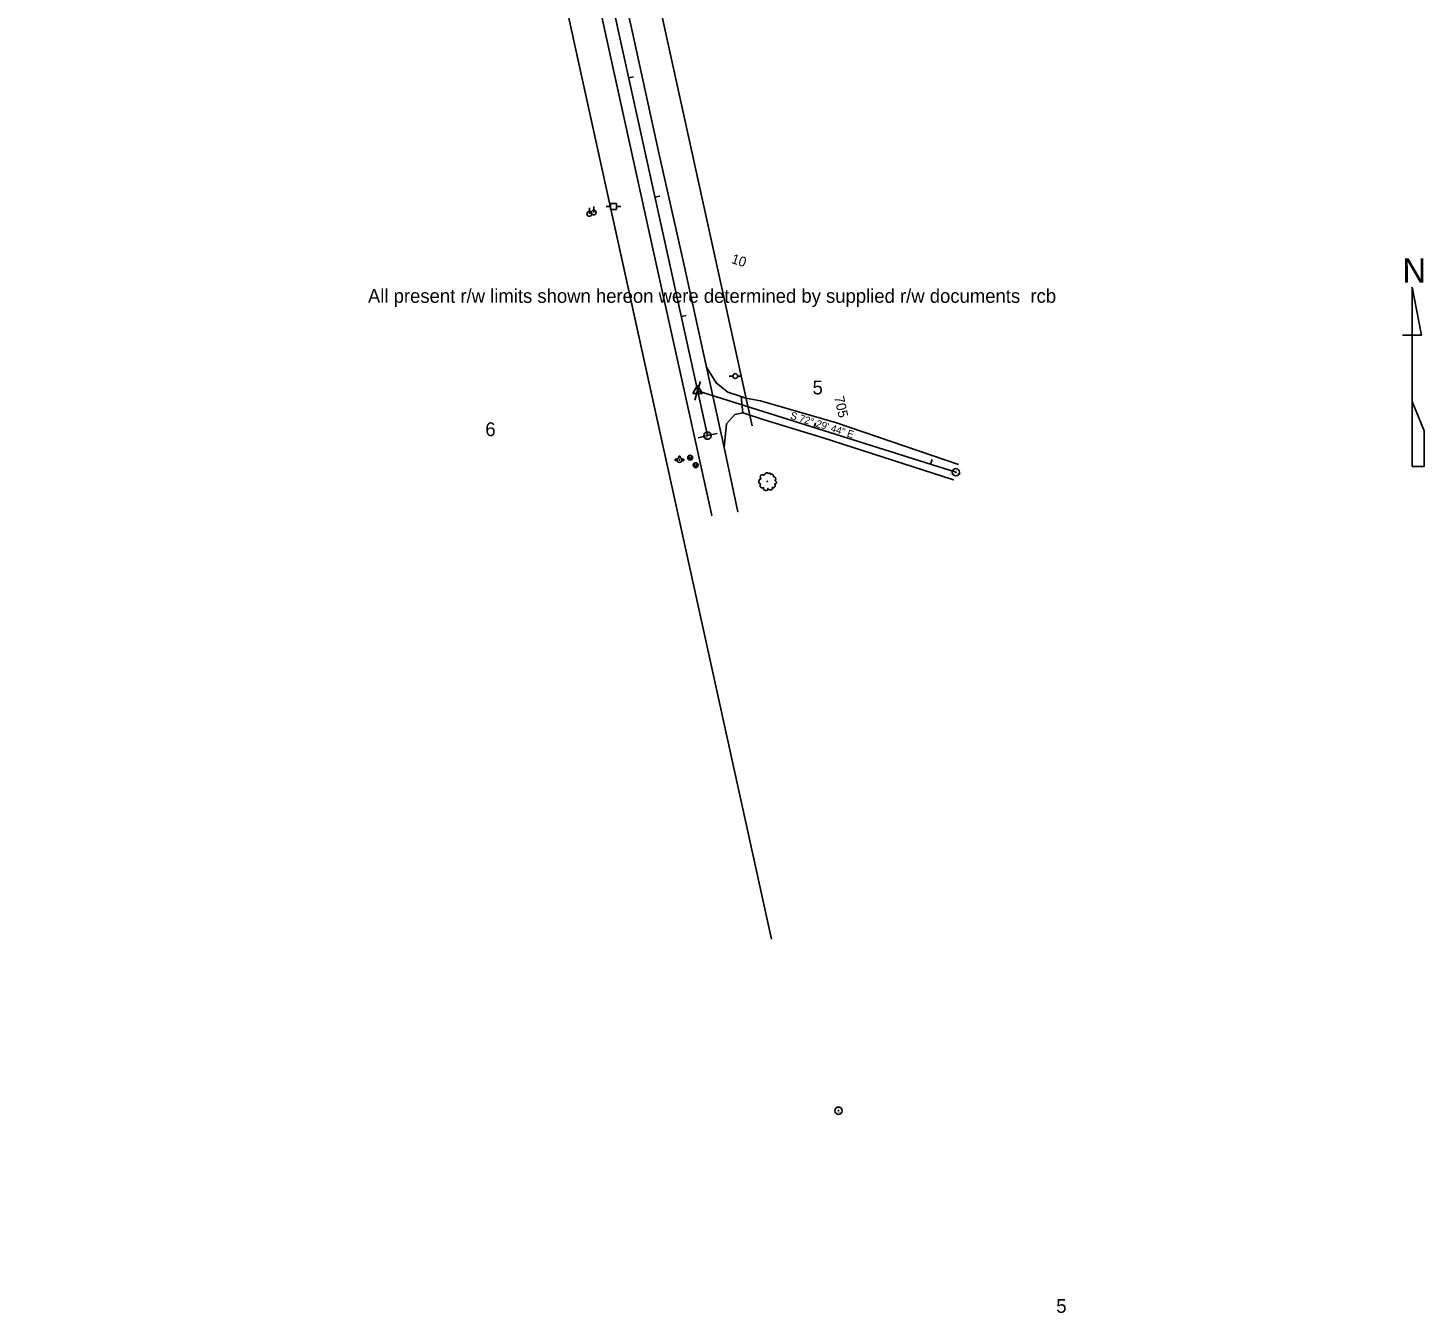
# Model space of a CAD drawing. Extents: x 2519952 to 2531965, y 848341 to 887632.
# Drawn here: x 2524339 to 2525482, y 867353 to 868406 of the extents above; entities that cross this region are included whole.
import ezdxf

# ---------------------------------------------------------------- set-up
doc = ezdxf.new("R2010")
doc.units = 0
for name, color, linetype in [('RD_EX_Driveway', 7, 'Continuous'), ('RD_EX_DV_Prop', 7, 'Continuous'), ('RD_EX_DV_TX_Prop', 7, 'Continuous'), ('RD_EX_Misc', 7, 'Continuous'), ('RD_EX_Road', 7, 'Continuous'), ('RD_EX_RW', 7, 'Continuous'), ('RD_EX_RW_TX', 7, 'Continuous'), ('RD_EX_UT', 7, 'Continuous'), ('RD_EX_VEG', 7, 'Continuous'), ('RD_HC_Cl', 7, 'Continuous'), ('RD_HC_Data', 7, 'Continuous'), ('RD_HC_Data_Tic', 7, 'Continuous'), ('RD_HC_TX_Sta50', 7, 'Continuous'), ('RD_HC_txCode', 7, 'Continuous'), ('RD_SMD_Locator', 7, 'Continuous')]:
    doc.layers.add(name, color=color, linetype=linetype)

msp = doc.modelspace()

# ---------------------------------------------------------------- linework, layer by layer
at = {"layer": 'RD_EX_Driveway'}
msp.add_lwpolyline([(2524908.9, 868062), (2524910.8, 868081.4), (2524917.6, 868088.9), (2524924.2, 868090.2), (2524922.6, 868103.6), (2524911.9, 868107.2), (2524902.2, 868114.9), (2524894.3, 868127.7)], dxfattribs=at)
at = {"layer": 'RD_EX_DV_Prop'}
for p, q in [((2524824.3, 868568), (2524931.8, 868079.7)), ((2524751.1, 868551.8), (2524947.7, 867659))]:
    msp.add_line(p, q, dxfattribs=at)
at = {"layer": 'RD_EX_Misc'}
for p, q in [((2525480, 868154), (2525472.2, 868193.2)), ((2525472.2, 868193.2), (2525472.2, 868193.2)), ((2525472.2, 868193.2), (2525472.2, 868154)), ((2525464.4, 868154), (2525472.2, 868154)), ((2525472.2, 868099.6), (2525472.2, 868154)), ((2525472.2, 868154), (2525480, 868154)), ((2525480, 868154), (2525480, 868154.4)), ((2525482, 868075.6), (2525472.2, 868099.6)), ((2525472.2, 868099.6), (2525472.2, 868046.2)), ((2525482, 868046.2), (2525482, 868075.8)), ((2525482, 868075.8), (2525482, 868075.6)), ((2525472.2, 868046.2), (2525482, 868046.2))]:
    msp.add_line(p, q, dxfattribs=at)
at = {"layer": 'RD_EX_Road'}
for p, q in [((2524812.4, 868397.3), (2524794.6, 868479.5)), ((2524833.7, 868401.8), (2524815.3, 868485.2)), ((2524834, 868299.3), (2524812.4, 868397.3)), ((2524855.1, 868304.4), (2524833.7, 868401.8)), ((2524875.7, 868212.3), (2524855.1, 868304.4)), ((2524854.3, 868207.4), (2524834, 868299.3)), ((2524874.4, 868116.3), (2524854.3, 868207.4)), ((2524894.3, 868127.7), (2524875.7, 868212.3)), ((2524908.9, 868062), (2524894.3, 868127.7)), ((2524898.7, 868006.1), (2524874.4, 868116.3)), ((2524920, 868009.2), (2524908.9, 868062))]:
    msp.add_line(p, q, dxfattribs=at)
for points in [[(2524922.6, 868103.6), (2524926.5, 868102.4), (2524938.6, 868100.2), (2525000.9, 868082.1), (2525100.6, 868048)], [(2524924.2, 868090.2), (2524941.6, 868084.5), (2524990, 868069.9), (2525096.7, 868035.4)]]:
    msp.add_lwpolyline(points, dxfattribs=at)
at = {"layer": 'RD_EX_RW'}
for p, q in [((2524824.3, 868568), (2524931.8, 868079.7)), ((2524751.1, 868551.8), (2524858.6, 868063.5))]:
    msp.add_line(p, q, dxfattribs=at)
at = {"layer": 'RD_EX_UT'}
for p, q in [((2524802, 868254.4), (2524802, 868259.4)), ((2524812.2, 868259.3), (2524815.6, 868259.3)), ((2524820.6, 868261.9), (2524815.6, 868261.9)), ((2524815.6, 868261.9), (2524815.6, 868256.9)), ((2524820.5, 868259.3), (2524824.2, 868259.3)), ((2524820.6, 868256.9), (2524820.6, 868261.9)), ((2524798.4, 868253.3), (2524798.4, 868258.3)), ((2524815.6, 868256.9), (2524820.6, 868256.9)), ((2524913, 868120.4), (2524915.9, 868120.4)), ((2524919.9, 868120.4), (2524923, 868120.4)), ((2524871.8, 868054.8), (2524871.8, 868053.6)), ((2524872.8, 868054.8), (2524871.8, 868054.8)), ((2524872.8, 868053.5), (2524872.8, 868054.8)), ((2524881, 868051.6), (2524879.7, 868055)), ((2524881, 868051.6), (2524882.3, 868055)), ((2524870.4, 868052.2), (2524868.8, 868052.2)), ((2524868.8, 868052.2), (2524868.8, 868051.2)), ((2524868.8, 868051.2), (2524870.3, 868051.2)), ((2524875.8, 868052.2), (2524874.2, 868052.2)), ((2524874.2, 868051.2), (2524875.8, 868051.2)), ((2524875.8, 868051.2), (2524875.8, 868052.2)), ((2524885.5, 868045.4), (2524884.2, 868048.8)), ((2524885.5, 868045.4), (2524886.9, 868048.8))]:
    msp.add_line(p, q, dxfattribs=at)
for centre, radius in [((2524798.4, 868253.3), 2), ((2524802, 868254.4), 2), ((2524917.9, 868120.4), 2), ((2524872.3, 868051.6), 2), ((2524881, 868053.6), 2), ((2524872.3, 868051.6), 0.25), ((2524885.5, 868047.4), 2)]:
    msp.add_circle(centre, radius, dxfattribs=at)
for start, end in [(74.2455, 103.2128), (163.3387, 192.315), (347.685, 16.6613)]:
    msp.add_arc((2524872.3, 868051.6), 2, start, end, dxfattribs=at)
at = {"layer": 'RD_EX_VEG'}
for centre, radius in [((2524944.1, 868034.1), 0.25), ((2524944, 868034), 0.0001)]:
    msp.add_circle(centre, radius, dxfattribs=at)
for points in [[(2524944.2, 868041.2), (2524943.9, 868041.2), (2524943.6, 868041.1), (2524943.3, 868041), (2524943.1, 868041), (2524942.9, 868040.9), (2524942.6, 868040.7), (2524942.3, 868040.5), (2524942.2, 868040.2), (2524942.2, 868040), (2524942.1, 868039.7), (2524942.1, 868039.6), (2524942, 868039.5), (2524941.8, 868039.6), (2524941.6, 868039.6), (2524941.3, 868039.6), (2524941.1, 868039.6), (2524940.7, 868039.6), (2524940.4, 868039.6), (2524940.1, 868039.6), (2524939.8, 868039.5), (2524939.4, 868039.4), (2524939.1, 868039.3), (2524938.8, 868039), (2524938.5, 868038.5), (2524938.4, 868038.2), (2524938.2, 868037.9), (2524938.4, 868037.5), (2524938.6, 868037.1), (2524938.6, 868036.9), (2524938.7, 868036.5), (2524938.8, 868036.3), (2524938.9, 868036.1), (2524938.8, 868036.1), (2524938.4, 868036), (2524938.1, 868035.9), (2524937.7, 868035.7), (2524937.5, 868035.5), (2524937.4, 868035.1), (2524937.4, 868034.8), (2524937.3, 868034.6), (2524937.2, 868034.3), (2524937.2, 868034.2), (2524937.1, 868033.9), (2524937.2, 868033.5), (2524937.2, 868033.1), (2524937.4, 868032.9), (2524937.5, 868032.7), (2524937.7, 868032.5), (2524938.1, 868032.2), (2524938.4, 868032.1), (2524938.6, 868032.1), (2524938.4, 868031.6), (2524938.4, 868031.3), (2524938.3, 868030.9), (2524938.3, 868030.8), (2524938.2, 868030.3), (2524938.4, 868030), (2524938.4, 868029.6), (2524938.6, 868029.4), (2524938.9, 868029.1), (2524939.2, 868028.9), (2524939.7, 868028.8), (2524940.1, 868028.8), (2524940.7, 868029), (2524940.9, 868029), (2524940.9, 868028.9), (2524940.9, 868028.5), (2524940.9, 868028.1), (2524941.1, 868027.7), (2524941.2, 868027.5), (2524941.3, 868027.2), (2524941.7, 868027), (2524942.1, 868026.9), (2524942.5, 868026.8), (2524942.9, 868026.7), (2524943.4, 868026.7), (2524944, 868026.8), (2524944.3, 868026.9), (2524944.4, 868027.1), (2524944.6, 868027.5), (2524944.6, 868027.7), (2524944.6, 868028.3), (2524944.7, 868028.1), (2524944.9, 868027.8), (2524945.4, 868027.5), (2524945.8, 868027.3), (2524946.2, 868027.2), (2524946.5, 868027.1), (2524947, 868027.2), (2524947.4, 868027.2), (2524947.8, 868027.4), (2524948.1, 868027.6), (2524948.2, 868027.9), (2524948.3, 868028.2), (2524948.4, 868028.6), (2524948.4, 868028.7)], [(2524948.4, 868028.7), (2524948.3, 868028.9), (2524948.3, 868029.2), (2524948.4, 868029.1), (2524948.5, 868029.1), (2524948.8, 868029), (2524949, 868028.9), (2524949.4, 868028.9), (2524949.6, 868029), (2524950.1, 868029.3), (2524950.4, 868029.8), (2524950.6, 868030.1), (2524950.7, 868030.5), (2524950.7, 868030.7), (2524950.6, 868031.2), (2524950.4, 868031.4), (2524950.4, 868031.6), (2524950.3, 868032), (2524950.4, 868032), (2524950.6, 868032.1), (2524951, 868032.2), (2524951.3, 868032.3), (2524951.5, 868032.5), (2524951.6, 868032.7), (2524951.6, 868033.1), (2524951.6, 868033.5), (2524951.5, 868033.7), (2524951.4, 868033.8), (2524951.4, 868034), (2524951.2, 868034.2), (2524951.1, 868034.3), (2524951, 868034.4), (2524950.9, 868034.6), (2524950.7, 868034.7), (2524950.6, 868034.7), (2524950.5, 868034.9), (2524950.7, 868035.1), (2524950.7, 868035.2), (2524950.7, 868035.4), (2524951, 868035.8), (2524951, 868036.2), (2524951, 868036.6), (2524950.9, 868036.9), (2524950.8, 868037.1), (2524950.6, 868037.4), (2524950.4, 868037.6), (2524950.3, 868037.7), (2524949.9, 868037.8), (2524949.7, 868037.9), (2524949.3, 868037.9), (2524949.1, 868037.9), (2524949.2, 868038), (2524949.2, 868038.1), (2524949.2, 868038.4), (2524949.1, 868038.8), (2524948.9, 868039.3), (2524948.9, 868039.4), (2524948.8, 868039.6), (2524948.6, 868039.8), (2524948.4, 868039.9), (2524948.2, 868040), (2524948, 868040.1), (2524947.7, 868040.1), (2524947.4, 868040), (2524947.2, 868039.9), (2524947, 868039.8), (2524947, 868039.9), (2524946.9, 868040.2), (2524946.8, 868040.4), (2524946.7, 868040.6), (2524946.4, 868040.8), (2524946, 868040.9), (2524945.4, 868040.8), (2524945.1, 868040.6), (2524944.9, 868040.4), (2524944.9, 868040.6), (2524944.7, 868040.8), (2524944.6, 868040.9), (2524944.4, 868041.1), (2524944.2, 868041.2), (2524944.1, 868041.2)]]:
    msp.add_spline(points, degree=3, dxfattribs=at)
at = {"layer": 'RD_HC_Cl'}
for p, q in [((2524338.6, 870599.2), (2524895.2, 868071.6)), ((2524887.1, 868108.3), (2525098.6, 868041.6))]:
    msp.add_line(p, q, dxfattribs=at)
at = {"layer": 'RD_HC_Data'}
for p, q in [((2524883.2, 868106), (2524887.1, 868112.9)), ((2524887.1, 868112.9), (2524891.1, 868106)), ((2524883.2, 868106), (2524891.1, 868106))]:
    msp.add_line(p, q, dxfattribs=at)
for centre, radius in [((2524887.1, 868108.3), 0.529), ((2524895.2, 868071.6), 3), ((2524895.2, 868071.6), 0.282), ((2525098.6, 868041.6), 3), ((2525098.6, 868041.6), 0.282), ((2525002.4, 867518.6), 3), ((2525002.4, 867518.6), 0.282)]:
    msp.add_circle(centre, radius, dxfattribs=at)
at = {"layer": 'RD_HC_Data_Tic'}
for p, q in [((2524830.7, 868364.6), (2524834.6, 868365.4)), ((2524852.2, 868266.9), (2524856.1, 868267.8)), ((2524873.7, 868169.2), (2524877.6, 868170.1)), ((2524887.1, 868108.3), (2524889.5, 868116)), ((2524887.1, 868108.3), (2524884.7, 868100.7)), ((2524982.5, 868078.2), (2524983.7, 868082.1)), ((2524895.2, 868071.6), (2524887.4, 868069.9)), ((2524895.2, 868071.6), (2524903, 868073.3)), ((2525077.9, 868048.2), (2525079.1, 868052))]:
    msp.add_line(p, q, dxfattribs=at)
at = {"layer": 'RD_SMD_Locator'}
for centre in [(2524812.4, 868397.3), (2524833.7, 868401.8), (2524855.1, 868304.4), (2524834, 868299.3), (2524854.3, 868207.4), (2524875.7, 868212.3), (2524894.3, 868127.7), (2524894.3, 868127.7), (2524874.4, 868116.3), (2524902.2, 868114.9), (2524887.1, 868108.3), (2524911.9, 868107.2), (2524922.6, 868103.6), (2524922.6, 868103.6), (2524926.5, 868102.4), (2524938.6, 868100.2), (2524917.6, 868088.9), (2524924.2, 868090.2), (2524924.2, 868090.2), (2524910.8, 868081.4), (2524941.6, 868084.5), (2525000.9, 868082.1), (2524895.2, 868071.6), (2524990, 868069.9), (2524908.9, 868062), (2524908.9, 868062), (2525098.6, 868041.6), (2525100.6, 868048), (2525096.7, 868035.4), (2524920, 868009.2), (2524898.7, 868006.1), (2525002.4, 867518.6)]:
    msp.add_circle(centre, 0.001, dxfattribs=at)

# ---------------------------------------------------------------- texts
at = {"layer": 'RD_EX_DV_TX_Prop'}
for s, p in [('5', (2524981.2, 868105.4)), ('6', (2524713.2, 868071.2)), ('5', (2525180.8, 867353))]:
    msp.add_text(s, height=11.3, dxfattribs=at).set_placement(p)
at = {"layer": 'RD_EX_Misc'}
msp.add_text('N', height=20, dxfattribs=at).set_placement((2525464.3, 868196.9))
at = {"layer": 'RD_EX_RW_TX'}
msp.add_text('All present r/w limits shown hereon were determined by supplied r/w documents  rcb', height=11.317, dxfattribs=at).set_placement((2524617.1, 868180.4))
at = {"layer": 'RD_HC_Data'}
msp.add_text('S 72%%d 29\' 44" E', height=6, rotation=342.4954, dxfattribs=at).set_placement((2524962.5, 868085.6))
at = {"layer": 'RD_HC_TX_Sta50'}
for s, rotation, p in [('10', 342.4954, (2524914.1, 868213.1)), ('705', 282.4185, (2524998.9, 868103.1))]:
    msp.add_text(s, height=8, rotation=rotation, dxfattribs=at).set_placement(p)
at = {"layer": 'RD_HC_txCode'}
for s, p in [('27', (2524886.4, 868109.3)), ('PI 10+00.00', (2524883.1, 868106.3)), ('POT 705+00.00', (2524889.4, 868069.6)), ('15', (2524894.8, 868072.6)), ('28', (2525097.9, 868042.6)), ('POT 12+21.76', (2525094, 868039.6)), ('CP 6 PSC', (2524998.8, 867516.6)), ('6', (2525002.1, 867519.6))]:
    msp.add_text(s, height=1, dxfattribs=at).set_placement(p)

doc.saveas('drawing.dxf')
